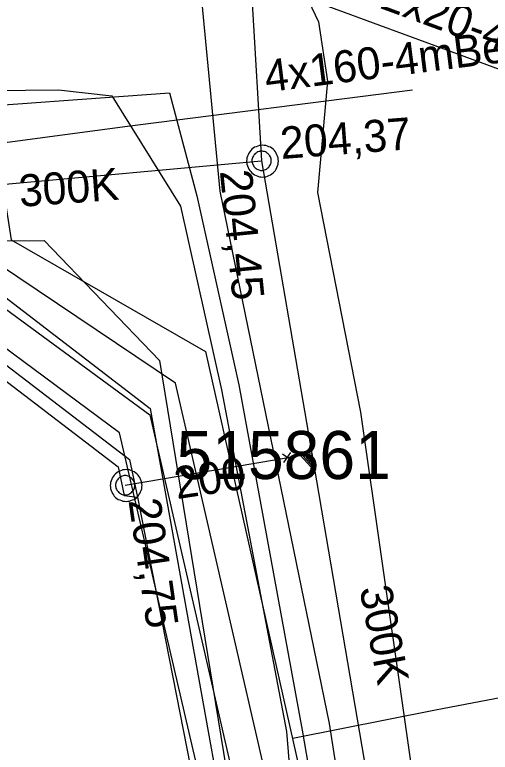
# Model space of a CAD drawing. Extents: x -746464 to -745690, y -1051581 to -1049993.
# Drawn here: x -746279.81 to -746264.96, y -1050912.12 to -1050889.08 of the extents above; entities that cross this region are included whole.
import ezdxf

# ---------------------------------------------------------------- set-up
doc = ezdxf.new("R2010")
doc.units = 0
for name, color, linetype in [('04_CETIN_neprovozovane', 7, 'Continuous'), ('04_CETIN_sdelovaci_podzem', 7, 'Continuous'), ('45_Eltodo_popisy', 7, 'Continuous'), ('45_Eltodo_vedeni_NN_zemni', 7, 'Continuous'), ('48_Prazs_plynarenska_STL', 7, 'Continuous'), ('51_PVaK_kanal_jednotna_neoverena poloha_pripojka', 7, 'Continuous'), ('51_PVaK_kanal_jednotna_overena poloha_rad', 7, 'Continuous'), ('51_PVaK_kanal_objekty', 7, 'Continuous'), ('51_PVaK_kanal_popisy', 7, 'Continuous'), ('51_PVaK_vodovod_overena poloha_rad', 7, 'Continuous'), ('55_PREdi_NN', 7, 'Continuous'), ('55_PREdi_NN_popisy', 7, 'Continuous'), ('55_PREdi_stavby_popisy', 7, 'Continuous')]:
    doc.layers.add(name, color=color, linetype=linetype)

msp = doc.modelspace()

# ---------------------------------------------------------------- linework, layer by layer
at = {"layer": '04_CETIN_neprovozovane'}
msp.add_lwpolyline([(-746280.76, -1050887.71), (-746278.03, -1050887.35), (-746272.07, -1050886.49), (-746271.04, -1050887.78), (-746270.32, -1050889.3), (-746270.04, -1050891.15), (-746270.35, -1050894.63)], dxfattribs=at)
at = {"layer": '04_CETIN_sdelovaci_podzem'}
for points in [[(-746270.35, -1050894.63), (-746269.01, -1050901.5), (-746266.32, -1050920.34)], [(-746293.54, -1050900.88), (-746282.93, -1050896.14), (-746278.89, -1050896.13), (-746275.29, -1050899.88), (-746271.37, -1050923.87), (-746270.82, -1050929.61), (-746270.71, -1050934.81), (-746270.84, -1050937.01), (-746270.97, -1050940.48), (-746271.75, -1050956.45), (-746272.12, -1050968.21), (-746272.31, -1050969.35), (-746272.98, -1050970.63), (-746277.41, -1050975.71), (-746284.7, -1050981.93), (-746291.28, -1050985.97), (-746303.6, -1050992.83)]]:
    msp.add_lwpolyline(points, dxfattribs=at)
at = {"layer": '45_Eltodo_vedeni_NN_zemni'}
for points in [[(-746278.957, -1050878.792), (-746278.902, -1050879.39), (-746278.616, -1050882.513), (-746280.683, -1050886.927), (-746285.118, -1050889.125), (-746280.733, -1050899.524), (-746276.221, -1050902.974), (-746275.975, -1050904.15)], [(-746287.042, -1050890.079), (-746285.454, -1050889.234), (-746281.061, -1050899.777), (-746276.582, -1050903.201), (-746276.394, -1050904.101), (-746275.975, -1050904.15)], [(-746275.975, -1050904.15), (-746271.355, -1050927.718)]]:
    msp.add_lwpolyline(points, dxfattribs=at)
at = {"layer": '48_Prazs_plynarenska_STL'}
for points in [[(-746327.22, -1050911.55), (-746303.85, -1050901.44), (-746298.25, -1050898.76), (-746294.08, -1050896.77), (-746286.88, -1050893.32), (-746285.964, -1050892.923), (-746282.58, -1050891.46), (-746278.44, -1050891.42), (-746276.78, -1050891.61)], [(-746276.78, -1050891.61), (-746274.63, -1050895.06), (-746273.35, -1050900.8), (-746271.32, -1050911.47), (-746270.01, -1050927.46), (-746269.84, -1050954.2), (-746270.23, -1050965.93), (-746271.24, -1050971.82), (-746272.86, -1050974.3), (-746273.57, -1050976.4), (-746273.63, -1050976.714)]]:
    msp.add_lwpolyline(points, dxfattribs=at)
at = {"layer": '51_PVaK_kanal_jednotna_neoverena poloha_pripojka'}
msp.add_line((-746276.36, -1050903.78), (-746270.536, -1050902.792), dxfattribs=at)
at = {"layer": '51_PVaK_kanal_jednotna_overena poloha_rad'}
for p in [(-746274.86, -1050847.58), (-746284.21, -1050894.74)]:
    msp.add_line(p, (-746272.1, -1050893.64), dxfattribs=at)
msp.add_lwpolyline([(-746272.1, -1050893.64), (-746270.536, -1050902.792), (-746266.51, -1050926.35)], dxfattribs=at)
at = {"layer": '51_PVaK_kanal_objekty'}
for p, q in [((-746271.408, -1050903.07), (-746271.185, -1050902.757)), ((-746271.135, -1050903.031), (-746271.446, -1050902.812))]:
    msp.add_line(p, q, dxfattribs=at)
for points in [[(-746271.57, -1050893.65), (-746271.58, -1050893.6), (-746271.58, -1050893.55), (-746271.6, -1050893.5), (-746271.62, -1050893.45), (-746271.64, -1050893.4), (-746271.67, -1050893.36), (-746271.7, -1050893.32), (-746271.74, -1050893.28), (-746271.78, -1050893.25), (-746271.82, -1050893.22), (-746271.87, -1050893.2), (-746271.92, -1050893.18), (-746271.97, -1050893.16), (-746272.02, -1050893.16), (-746272.07, -1050893.15), (-746272.12, -1050893.16), (-746272.17, -1050893.16), (-746272.22, -1050893.18), (-746272.27, -1050893.2), (-746272.32, -1050893.22), (-746272.36, -1050893.25), (-746272.4, -1050893.28), (-746272.44, -1050893.32), (-746272.47, -1050893.36), (-746272.5, -1050893.4), (-746272.52, -1050893.45), (-746272.54, -1050893.5), (-746272.56, -1050893.55), (-746272.56, -1050893.6), (-746272.57, -1050893.65), (-746272.56, -1050893.7), (-746272.56, -1050893.75), (-746272.54, -1050893.8), (-746272.52, -1050893.85), (-746272.5, -1050893.9), (-746272.47, -1050893.94), (-746272.44, -1050893.98), (-746272.4, -1050894.02), (-746272.36, -1050894.05), (-746272.32, -1050894.08), (-746272.27, -1050894.1), (-746272.22, -1050894.12), (-746272.17, -1050894.14), (-746272.12, -1050894.14), (-746272.07, -1050894.15), (-746272.02, -1050894.14), (-746271.97, -1050894.14), (-746271.92, -1050894.12), (-746271.87, -1050894.1), (-746271.82, -1050894.08), (-746271.78, -1050894.05), (-746271.74, -1050894.02), (-746271.7, -1050893.98), (-746271.67, -1050893.94), (-746271.64, -1050893.9), (-746271.62, -1050893.85), (-746271.6, -1050893.8), (-746271.58, -1050893.75), (-746271.58, -1050893.7), (-746271.57, -1050893.65)], [(-746271.8, -1050893.64), (-746271.8, -1050893.61), (-746271.806, -1050893.58), (-746271.812, -1050893.55), (-746271.824, -1050893.52), (-746271.842, -1050893.49), (-746271.86, -1050893.466), (-746271.878, -1050893.442), (-746271.902, -1050893.418), (-746271.926, -1050893.4), (-746271.95, -1050893.382), (-746271.98, -1050893.364), (-746272.01, -1050893.352), (-746272.04, -1050893.346), (-746272.07, -1050893.34), (-746272.1, -1050893.34), (-746272.13, -1050893.34), (-746272.16, -1050893.346), (-746272.19, -1050893.352), (-746272.22, -1050893.364), (-746272.25, -1050893.382), (-746272.274, -1050893.4), (-746272.298, -1050893.418), (-746272.322, -1050893.442), (-746272.34, -1050893.466), (-746272.358, -1050893.49), (-746272.376, -1050893.52), (-746272.388, -1050893.55), (-746272.394, -1050893.58), (-746272.4, -1050893.61), (-746272.4, -1050893.64), (-746272.4, -1050893.67), (-746272.394, -1050893.7), (-746272.388, -1050893.73), (-746272.376, -1050893.76), (-746272.358, -1050893.79), (-746272.34, -1050893.814), (-746272.322, -1050893.838), (-746272.298, -1050893.862), (-746272.274, -1050893.88), (-746272.25, -1050893.898), (-746272.22, -1050893.916), (-746272.19, -1050893.928), (-746272.16, -1050893.934), (-746272.13, -1050893.94), (-746272.1, -1050893.94), (-746272.07, -1050893.94), (-746272.04, -1050893.934), (-746272.01, -1050893.928), (-746271.98, -1050893.916), (-746271.95, -1050893.898), (-746271.926, -1050893.88), (-746271.902, -1050893.862), (-746271.878, -1050893.838), (-746271.86, -1050893.814), (-746271.842, -1050893.79), (-746271.824, -1050893.76), (-746271.812, -1050893.73), (-746271.806, -1050893.7), (-746271.8, -1050893.67), (-746271.8, -1050893.64)], [(-746271.298, -1050902.917), (-746270.539, -1050902.788), (-746270.446, -1050903.329), (-746270.881, -1050902.846)], [(-746270.798, -1050902.873), (-746270.577, -1050902.835), (-746270.518, -1050903.181), (-746270.799, -1050902.869)], [(-746270.712, -1050902.899), (-746270.601, -1050902.88), (-746270.571, -1050903.058), (-746270.712, -1050902.896)], [(-746275.83, -1050903.79), (-746275.84, -1050903.74), (-746275.84, -1050903.69), (-746275.86, -1050903.64), (-746275.88, -1050903.59), (-746275.9, -1050903.54), (-746275.93, -1050903.5), (-746275.96, -1050903.46), (-746276, -1050903.42), (-746276.04, -1050903.39), (-746276.08, -1050903.36), (-746276.13, -1050903.34), (-746276.18, -1050903.32), (-746276.23, -1050903.3), (-746276.28, -1050903.3), (-746276.33, -1050903.29), (-746276.38, -1050903.3), (-746276.43, -1050903.3), (-746276.48, -1050903.32), (-746276.53, -1050903.34), (-746276.58, -1050903.36), (-746276.62, -1050903.39), (-746276.66, -1050903.42), (-746276.7, -1050903.46), (-746276.73, -1050903.5), (-746276.76, -1050903.54), (-746276.78, -1050903.59), (-746276.8, -1050903.64), (-746276.82, -1050903.69), (-746276.82, -1050903.74), (-746276.83, -1050903.79), (-746276.82, -1050903.84), (-746276.82, -1050903.89), (-746276.8, -1050903.94), (-746276.78, -1050903.99), (-746276.76, -1050904.04), (-746276.73, -1050904.08), (-746276.7, -1050904.12), (-746276.66, -1050904.16), (-746276.62, -1050904.19), (-746276.58, -1050904.22), (-746276.53, -1050904.24), (-746276.48, -1050904.26), (-746276.43, -1050904.28), (-746276.38, -1050904.28), (-746276.33, -1050904.29), (-746276.28, -1050904.28), (-746276.23, -1050904.28), (-746276.18, -1050904.26), (-746276.13, -1050904.24), (-746276.08, -1050904.22), (-746276.04, -1050904.19), (-746276, -1050904.16), (-746275.96, -1050904.12), (-746275.93, -1050904.08), (-746275.9, -1050904.04), (-746275.88, -1050903.99), (-746275.86, -1050903.94), (-746275.84, -1050903.89), (-746275.84, -1050903.84), (-746275.83, -1050903.79)], [(-746276.06, -1050903.78), (-746276.06, -1050903.75), (-746276.066, -1050903.72), (-746276.072, -1050903.69), (-746276.084, -1050903.66), (-746276.102, -1050903.63), (-746276.12, -1050903.606), (-746276.138, -1050903.582), (-746276.162, -1050903.558), (-746276.186, -1050903.54), (-746276.21, -1050903.522), (-746276.24, -1050903.504), (-746276.27, -1050903.492), (-746276.3, -1050903.486), (-746276.33, -1050903.48), (-746276.36, -1050903.48), (-746276.39, -1050903.48), (-746276.42, -1050903.486), (-746276.45, -1050903.492), (-746276.48, -1050903.504), (-746276.51, -1050903.522), (-746276.534, -1050903.54), (-746276.558, -1050903.558), (-746276.582, -1050903.582), (-746276.6, -1050903.606), (-746276.618, -1050903.63), (-746276.636, -1050903.66), (-746276.648, -1050903.69), (-746276.654, -1050903.72), (-746276.66, -1050903.75), (-746276.66, -1050903.78), (-746276.66, -1050903.81), (-746276.654, -1050903.84), (-746276.648, -1050903.87), (-746276.636, -1050903.9), (-746276.618, -1050903.93), (-746276.6, -1050903.954), (-746276.582, -1050903.978), (-746276.558, -1050904.002), (-746276.534, -1050904.02), (-746276.51, -1050904.038), (-746276.48, -1050904.056), (-746276.45, -1050904.068), (-746276.42, -1050904.074), (-746276.39, -1050904.08), (-746276.36, -1050904.08), (-746276.33, -1050904.08), (-746276.3, -1050904.074), (-746276.27, -1050904.068), (-746276.24, -1050904.056), (-746276.21, -1050904.038), (-746276.186, -1050904.02), (-746276.162, -1050904.002), (-746276.138, -1050903.978), (-746276.12, -1050903.954), (-746276.102, -1050903.93), (-746276.084, -1050903.9), (-746276.072, -1050903.87), (-746276.066, -1050903.84), (-746276.06, -1050903.81), (-746276.06, -1050903.78)]]:
    msp.add_lwpolyline(points, dxfattribs=at)
at = {"layer": '51_PVaK_vodovod_overena poloha_rad'}
for points in [[(-746278.41, -1050989.48), (-746275.09, -1050983.09), (-746271.71, -1050974.46), (-746270.66, -1050972.01), (-746268.96, -1050966.25), (-746269.01, -1050954.31), (-746267.53, -1050945.14), (-746267.62, -1050927.16), (-746268.73, -1050919.25), (-746269.98, -1050911.22), (-746273.39, -1050894.59), (-746274.36, -1050884.47), (-746275.7, -1050870.82)], [(-746284.54, -1050892.94), (-746282.45, -1050892.06), (-746274.98, -1050891.52), (-746274.12, -1050894.74), (-746272.81, -1050900.64), (-746270.83, -1050911.43), (-746269.47, -1050919.39), (-746268.42, -1050927.25), (-746268.31, -1050945.14), (-746269.35, -1050954.19), (-746269.67, -1050966.06), (-746270.92, -1050971.92), (-746272.36, -1050974.54), (-746272.92, -1050976)]]:
    msp.add_lwpolyline(points, dxfattribs=at)
at = {"layer": '55_PREdi_NN'}
for points in [[(-746279.169, -1050871.142), (-746277.57, -1050883.025), (-746280.866, -1050890.088), (-746279.924, -1050896.114), (-746273.849, -1050899.599), (-746267.956, -1050925.842), (-746268.166, -1050933.051)], [(-746317.039, -1051026.572), (-746318.823, -1051026.486), (-746327.536, -1051014.504), (-746311.76, -1051000.614), (-746293.31, -1050989.459), (-746270.27, -1050970.787), (-746268.96, -1050925.936), (-746274.791, -1050900.587), (-746280.96, -1050896.444), (-746281.902, -1050889.994), (-746278.512, -1050882.884), (-746280.08, -1050871.671), (-746281.012, -1050871.801)], [(-746282.685, -1050891.909), (-746281.949, -1050896.915), (-746275.592, -1050901.576), (-746269.964, -1050926.03), (-746271.259, -1050970.363), (-746293.852, -1050988.609), (-746312.231, -1050999.532), (-746328.24, -1051013.684), (-746340.582, -1051017.778)], [(-746281.522, -1050896.823), (-746275.585, -1050901.38), (-746271.721, -1050922.906), (-746271.42, -1050926.91)], [(-746272.675, -1050926.661), (-746271.04, -1050926.567), (-746270.968, -1050926.124), (-746276.534, -1050902.141), (-746282.891, -1050897.433), (-746294.264, -1050901.541), (-746298.855, -1050903.485), (-746297.971, -1050905.573)]]:
    msp.add_lwpolyline(points, dxfattribs=at)
at = {"layer": '55_PREdi_NN_popisy'}
msp.add_lwpolyline([(-746271.127, -1050911.68), (-746266.671, -1050910.795), (-746257.893, -1050909.122)], dxfattribs=at)
at = {"layer": '55_PREdi_stavby_popisy'}
for points in [[(-746278.799, -1050885.598), (-746272.867, -1050887.753), (-746264.369, -1050890.894)], [(-746281.52, -1050893.257), (-746276.374, -1050892.569), (-746267.387, -1050891.428)]]:
    msp.add_lwpolyline(points, dxfattribs=at)

# ---------------------------------------------------------------- texts
at = {"layer": '45_Eltodo_popisy'}
msp.add_text('515861', height=1.5, dxfattribs=at).set_placement((-746274.757, -1050903.585))
at = {"layer": '51_PVaK_kanal_popisy'}
for s, rotation, p in [('204,37', 4.3738, (-746271.483, -1050893.587)), ('300K', 4.19, (-746279.644, -1050895.082)), ('204,45', 275.6955, (-746273.405, -1050893.965)), ('200', 8.629, (-746274.747, -1050904.215)), ('204,75', 278.2423, (-746276.26, -1050904.253)), ('300K', 280.6981, (-746269.046, -1050907.003))]:
    msp.add_text(s, height=1, rotation=rotation, dxfattribs=at).set_placement(p)
at = {"layer": '55_PREdi_stavby_popisy'}
for s, rotation, p in [('2x20-4.0mBet. r.', 339.7188, (-746268.445, -1050888.855)), ('4x160-4mBet. r.', 7.2361, (-746271.944, -1050891.502))]:
    msp.add_text(s, height=1, rotation=rotation, dxfattribs=at).set_placement(p)

doc.saveas('drawing.dxf')
